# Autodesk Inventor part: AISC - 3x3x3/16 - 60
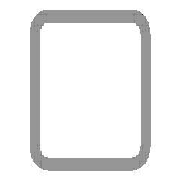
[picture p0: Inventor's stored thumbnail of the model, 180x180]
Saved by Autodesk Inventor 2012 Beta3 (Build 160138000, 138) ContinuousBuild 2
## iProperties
_CCFamilyMember: 9
_CCFamilyDisplayName: ANSI AISC (Square) - Tube
_FrameMemberDoc: Frame Member File
_Version: 15.0.0
_GetPNFromCC: 1
Created: 2011-01
Part Number: AISC - 3x3x3/16 - 60
Material: Steel, Mild
Description: Tube
Document SubType Name: Modeling
Standard: ANSI
Designer: Beta-8540w
Standards Organization: ANSI
Language: en-US
Size Designation: 3x3x3/16
Categories: <MemberInstance><Categories><Category DisplayName="Structural Shapes" InternalName="089c4875-fa83-4c05-b084-43b9cc11f5ed" Mnemonic="GRDR"><CategoryParameter Dis
Stock Number: 3x3x3/16
Density: 7.86 g/cm^3
IsCustomPart: 1
G_L: 60.000 in
G_W: 3.000 in
G_H: 3.000 in
Author: Beta-8540w
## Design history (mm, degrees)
node "Start plane"
node "End plane"
sketch "Sketch"
  geometry: L1 (-38.1, -28.575)-(-38.1, 28.575); L2 (-28.575, 38.1)-(28.575, 38.1); L3 (38.1, 28.575)-(38.1, -28.575); L4 (28.575, -38.1)-(-28.575, -38.1); L5 (-28.575, 33.337)-(28.575, 33.338); L6 (33.338, 28.575)-(33.338, -28.575); L7 (28.575, -33.337)-(-28.575, -33.338); L8 (-33.338, -28.575)-(-33.338, 28.575); L9 (0, 56.102)-(0, -56.102) reference; L10 (-56.102, 0)-(56.102, 0) reference; A1 r 9.525 centre (-28.575, -28.575) between (-38.1, -28.575) and (-28.575, -38.1); A2 r 9.525 centre (-28.575, 28.575) between (-28.575, 38.1) and (-38.1, 28.575); A3 r 9.525 centre (28.575, 28.575) between (38.1, 28.575) and (28.575, 38.1); A4 r 9.525 centre (28.575, -28.575) between (28.575, -38.1) and (38.1, -28.575); A5 r 4.763 centre (-28.575, 28.575) between (-28.575, 33.337) and (-33.338, 28.575); A6 r 4.763 centre (28.575, 28.575) between (33.338, 28.575) and (28.575, 33.338); A7 r 4.763 centre (28.575, -28.575) between (28.575, -33.337) and (33.338, -28.575); A8 r 4.763 centre (-28.575, -28.575) between (-33.338, -28.575) and (-28.575, -33.338)
  constraints: 16 end point, 16 point on circle, 8 centre point, 8 tangent, 4 parallel, 3 equal radius, 2 perpendicular, 7 other
  dimensions: "d10" = 76.2 distance between parallel lines of L2 L4 (= G_H); "d11" = 76.2 distance between parallel lines of L1 L3 (= G_W); "d12" = 4.7625 distance between parallel lines of L3 L6 (= G_T); "d15" = 38.1 distance between parallel lines of L2 L10 (= 0.5 x d10); "d16" = 38.1 distance between parallel lines of L9 L3 (= 0.5 x d11); "d17" = 9.525 radius of A1 (= G_IR)
extrude "Body" new body sketch "Sketch" stored distance "d3" = 1524 (= G_L); taper "d4" = 0 deg
node "Driven Length"
  sketch "Sketch3"
    geometry: L1 (0, 0)-(10, 0) reference
    constraints: 2 end point, 1 horizontal
  workplane "Work Plane3"
  sketch "Sketch4"
    geometry: L1 (-2, 0)-(12, 0) reference; L2 (-2, 1524)-(12, 1524) reference
    dimensions: "d19" = 1524 distance between parallel lines of L1 L2 (derived)
body "Solid1"
other parameters: "G_W" = 76.2 [user parameter; used in 1 equation term], "G_H" = 76.2 [user parameter; used in 1 equation term], "G_T" = 4.7625 [user parameter; used in 1 equation term], "G_IR" = 9.525 [user parameter; used in 1 equation term], "G_L" = 1524 (= d19) [user parameter; used in 1 equation term], "G_OFFSET_START" = 0 [user parameter; used in 1 equation term], "G_OFFSET_END" = 0 [user parameter; used in 1 equation term], "d13" = 0 (computed from G_OFFSET_START), "d14" = 1524 (= G_OFFSET_END + B_L), "B_L" = 1524 [user parameter; used in 1 equation term], "d18" = 90 deg
